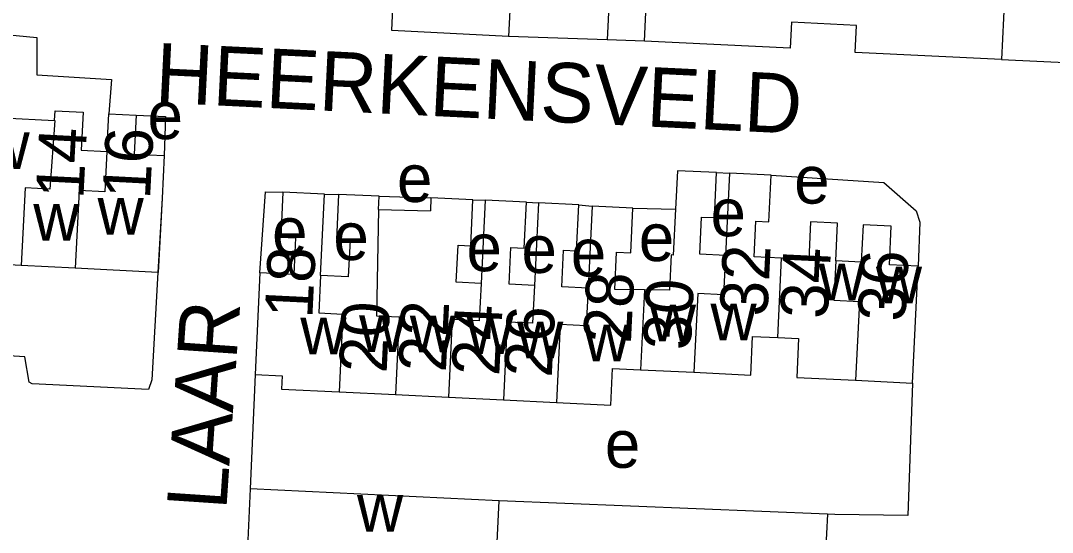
# Model space of a CAD drawing. Extents: x 163026 to 166241, y 382475 to 384501.
# Drawn here: x 164375.5 to 164462, y 383742 to 383784.9 of the extents above; entities that cross this region are included whole.
import ezdxf

# ---------------------------------------------------------------- set-up
doc = ezdxf.new("R2010")
doc.units = 0
for name, color, linetype in [('BLT_Basislijn', 7, 'Continuous'), ('BLT_Bebouwing', 7, 'Continuous'), ('BLT_Centroide', 7, 'Continuous'), ('BLT_Huisnummer', 7, 'Continuous'), ('BLT_Huisnummer_ tussenligend', 7, 'Continuous'), ('BLT_Onderverdeling_panden', 7, 'Continuous'), ('BLT_Straatnaam', 7, 'Continuous')]:
    doc.layers.add(name, color=color, linetype=linetype)

msp = doc.modelspace()

# ---------------------------------------------------------------- linework, layer by layer
at = {"layer": 'BLT_Basislijn'}
for p, q in [((164424.614, 383783.299), (164416.356, 383783.582)), ((164427.758, 383783.191), (164424.614, 383783.299)), ((164457.682, 383781.642), (164463.611, 383781.358)), ((164433.798, 383772.157), (164434.873, 383772.105)), ((164387.308, 383770.014), (164386.961, 383763.762)), ((164400.935, 383770.341), (164402.116, 383770.33)), ((164405.506, 383770.166), (164409.857, 383770.041)), ((164413.373, 383769.87), (164414.4, 383769.834)), ((164417.861, 383769.666), (164418.862, 383769.606)), ((164422.246, 383769.442), (164423.364, 383769.334)), ((164426.791, 383769.168), (164430.358, 383769.099)), ((164395.12, 383755.208), (164394.704, 383745.621)), ((164443.101, 383743.488), (164415.579, 383744.613)), ((164443.101, 383743.488), (164442.919, 383740.26))]:
    msp.add_line(p, q, dxfattribs=at)
for points in [[(164422.167, 383835.909), (164431.749, 383835.494), (164430.679, 383813.13), (164426.089, 383812.971), (164424.614, 383783.299)], [(164362.913, 383784.833), (164376.817, 383783.477), (164376.818, 383780.367), (164383.073, 383779.953), (164382.845, 383777.091)], [(164385.145, 383776.97), (164387.594, 383776.85), (164387.495, 383773.579)], [(164438.364, 383771.936), (164447.831, 383771.316), (164450.521, 383768.939), (164450.84, 383767.983), (164450.688, 383764.303)], [(164395.508, 383763.752), (164395.992, 383770.554), (164397.445, 383770.509)], [(164386.961, 383763.762), (164386.462, 383754.756), (164386.188, 383753.96), (164376.435, 383754.438), (164376.18, 383754.565), (164375.817, 383756.701), (164366.332, 383757.281), (164366.085, 383757.295)], [(164450.213, 383754.502), (164449.833, 383743.398), (164443.726, 383743.462), (164443.101, 383743.488)]]:
    msp.add_lwpolyline(points, dxfattribs=at)
at = {"layer": 'BLT_Bebouwing'}
for p, q in [((164427.758, 383783.191), (164428.052, 383789.269)), ((164416.605, 383788.423), (164416.356, 383783.582)), ((164457.968, 383787.548), (164457.682, 383781.642)), ((164382.845, 383777.091), (164385.145, 383776.97)), ((164387.495, 383773.579), (164387.308, 383770.014)), ((164438.364, 383771.936), (164434.873, 383772.105)), ((164400.935, 383770.341), (164397.445, 383770.509)), ((164387.308, 383770.014), (164386.98, 383763.761)), ((164405.506, 383770.166), (164402.116, 383770.33)), ((164405.453, 383769.068), (164405.506, 383770.166)), ((164409.857, 383770.041), (164409.804, 383768.943)), ((164413.373, 383769.87), (164409.857, 383770.041)), ((164417.861, 383769.666), (164414.4, 383769.834)), ((164422.246, 383769.442), (164418.862, 383769.606)), ((164405.453, 383769.068), (164407.635, 383769.005)), ((164407.635, 383769.005), (164409.804, 383768.943)), ((164426.791, 383769.168), (164423.364, 383769.334)), ((164375.486, 383764.362), (164371.004, 383764.598)), ((164380.014, 383764.126), (164375.486, 383764.362)), ((164450.213, 383754.502), (164450.688, 383764.303)), ((164386.961, 383763.762), (164380.014, 383764.126)), ((164386.98, 383763.761), (164386.961, 383763.762)), ((164395.508, 383763.752), (164395.12, 383755.208)), ((164427.424, 383755.616), (164431.894, 383755.4)), ((164445.46, 383754.731), (164450.213, 383754.502)), ((164402.148, 383753.757), (164406.887, 383753.529)), ((164406.887, 383753.529), (164411.313, 383753.314)), ((164411.313, 383753.314), (164415.929, 383753.09)), ((164415.929, 383753.09), (164420.371, 383752.875)), ((164415.579, 383744.613), (164394.704, 383745.621)), ((164415.282, 383738.463), (164415.579, 383744.613))]:
    msp.add_line(p, q, dxfattribs=at)
for points in [[(164416.356, 383783.582), (164406.572, 383784.084), (164406.7, 383786.582), (164403.505, 383786.746)], [(164457.682, 383781.642), (164445.43, 383782.234), (164445.54, 383784.503), (164440.079, 383784.767), (164439.974, 383782.601), (164427.758, 383783.191)], [(164369.365, 383774.53), (164371.532, 383774.415), (164371.698, 383777.591), (164373.995, 383777.471), (164373.958, 383776.753), (164378.299, 383776.527)], [(164378.299, 383776.527), (164378.342, 383777.336), (164380.695, 383777.213), (164380.529, 383774.043), (164382.68, 383773.93)], [(164382.68, 383773.93), (164382.845, 383777.091)], [(164385.145, 383776.97), (164384.975, 383773.711), (164387.495, 383773.579)], [(164433.798, 383772.157), (164430.514, 383772.316), (164430.358, 383769.099)], [(164434.539, 383765.198), (164432.387, 383765.302), (164432.538, 383768.427), (164433.615, 383768.375), (164433.798, 383772.157)], [(164434.873, 383772.105), (164434.539, 383765.198)], [(164439.248, 383764.962), (164436.959, 383765.074), (164437.104, 383768.07), (164438.174, 383768.018), (164438.364, 383771.936)], [(164397.445, 383770.509), (164397.262, 383766.731), (164398.495, 383766.671), (164398.347, 383763.615), (164395.508, 383763.752)], [(164400.605, 383763.53), (164400.935, 383770.341)], [(164402.116, 383770.33), (164401.932, 383766.544), (164403.069, 383766.489), (164402.921, 383763.418), (164400.605, 383763.53)], [(164414.06, 383762.855), (164411.981, 383762.955), (164412.131, 383766.056), (164413.185, 383766.005), (164413.373, 383769.87)], [(164414.4, 383769.834), (164414.06, 383762.855)], [(164418.525, 383762.695), (164416.406, 383762.798), (164416.554, 383765.861), (164417.675, 383765.807), (164417.861, 383769.666)], [(164418.862, 383769.606), (164418.525, 383762.695)], [(164423.03, 383762.465), (164420.829, 383762.574), (164420.977, 383765.642), (164422.06, 383765.59), (164422.246, 383769.442)], [(164423.364, 383769.334), (164423.03, 383762.465)], [(164427.745, 383762.311), (164425.267, 383762.339), (164425.419, 383765.489), (164426.61, 383765.432), (164426.791, 383769.168)], [(164430.358, 383769.099), (164430.171, 383765.236), (164430.001, 383765.244), (164429.858, 383762.287), (164427.745, 383762.311)], [(164443.79, 383764.745), (164443.944, 383767.916), (164441.687, 383768.026), (164441.533, 383764.852), (164439.248, 383764.962)], [(164450.688, 383764.303), (164448.287, 383764.419), (164448.443, 383767.657), (164446.085, 383767.771), (164445.934, 383764.642), (164443.79, 383764.745)], [(164431.894, 383755.4), (164436.664, 383755.169), (164436.821, 383758.411), (164438.927, 383758.309)], [(164438.927, 383758.309), (164440.679, 383758.224), (164440.522, 383754.971), (164445.46, 383754.731)], [(164420.371, 383752.875), (164424.923, 383752.656), (164425.072, 383755.73), (164427.424, 383755.616)], [(164395.12, 383755.208), (164397.386, 383755.1), (164397.332, 383753.992), (164402.148, 383753.757)], [(164394.704, 383745.621), (164394.407, 383739.471), (164415.282, 383738.463)]]:
    msp.add_lwpolyline(points, dxfattribs=at)
at = {"layer": 'BLT_Onderverdeling_panden'}
for p, q in [((164438.927, 383758.309), (164439.248, 383764.962)), ((164427.745, 383762.311), (164427.424, 383755.616))]:
    msp.add_line(p, q, dxfattribs=at)
for points in [[(164378.299, 383776.527), (164378.326, 383776.526), (164377.898, 383770.774), (164375.828, 383770.883), (164375.486, 383764.362)], [(164382.68, 383773.93), (164382.503, 383770.532), (164380.353, 383770.645), (164380.014, 383764.126)], [(164405.453, 383769.068), (164405.297, 383760.142), (164407.195, 383760.052), (164406.887, 383753.529)], [(164434.539, 383765.198), (164434.38, 383761.897), (164432.222, 383762.004), (164431.894, 383755.4)], [(164443.79, 383764.745), (164443.629, 383761.453), (164445.777, 383761.35), (164445.46, 383754.731)], [(164400.605, 383763.53), (164400.452, 383760.378), (164402.467, 383760.28), (164402.148, 383753.757)], [(164414.06, 383762.855), (164413.908, 383759.727), (164411.629, 383759.838), (164411.313, 383753.314)], [(164418.525, 383762.695), (164418.371, 383759.511), (164416.249, 383759.614), (164415.929, 383753.09)], [(164423.03, 383762.465), (164422.875, 383759.293), (164420.68, 383759.4), (164420.371, 383752.875)]]:
    msp.add_lwpolyline(points, dxfattribs=at)

# ---------------------------------------------------------------- texts
at = {"layer": 'BLT_Centroide'}
for s, p in [('e', (164386.094, 383774.963)), ('w', (164372.346, 383772.467)), ('e', (164407.004, 383769.686)), ('e', (164440.305, 383769.556)), ('w', (164376.521, 383766.437)), ('w', (164381.906, 383766.943)), ('e', (164433.29, 383766.818)), ('e', (164396.532, 383765.25)), ('e', (164401.677, 383764.818)), ('e', (164427.278, 383764.733)), ('e', (164412.834, 383763.882)), ('e', (164417.44, 383763.738)), ('e', (164421.579, 383763.45)), ('w', (164442.359, 383761.438)), ('w', (164447.156, 383761.188)), ('w', (164428.204, 383757.999)), ('w', (164433.29, 383758.087)), ('w', (164403.828, 383757.116)), ('w', (164408.083, 383757.08)), ('w', (164412.87, 383756.936)), ('w', (164398.906, 383756.9)), ('w', (164417.081, 383756.576)), ('w', (164422.659, 383756.324)), ('e', (164424.433, 383747.389)), ('w', (164403.659, 383742.031))]:
    msp.add_text(s, height=4, dxfattribs=at).set_placement(p)
at = {"layer": 'BLT_Huisnummer'}
for s, height, rotation, p in [('16', 4, 87.01183, (164386.297, 383769.871)), ('18', 3.9999, 87.23147, (164399.905, 383759.875)), ('36', 3.9999, 87.23147, (164449.617, 383759.609)), ('30', 3.9999, 87.23147, (164431.617, 383757.206)), ('22', 3.9999, 87.23147, (164411.102, 383755.366)), ('26', 3.9999, 87.23147, (164419.977, 383754.926))]:
    msp.add_text(s, height=height, rotation=rotation, dxfattribs=at).set_placement(p)
at = {"layer": 'BLT_Huisnummer_ tussenligend'}
for s, height, rotation, p in [('14', 4, 87.01183, (164380.708, 383769.896)), ('32', 3.9999, 87.23147, (164438.051, 383760.04)), ('34', 3.9999, 87.23147, (164443.106, 383759.836)), ('28', 3.9999, 87.23147, (164426.614, 383757.772)), ('20', 3.9999, 87.23147, (164406.133, 383755.289)), ('24', 3.9999, 87.23147, (164415.576, 383755.051))]:
    msp.add_text(s, height=height, rotation=rotation, dxfattribs=at).set_placement(p)
at = {"layer": 'BLT_Straatnaam'}
for s, rotation, p in [('HEERKENSVELD', 357.19478, (164386.662, 383778.047)), ('LAAR', 86.1433, (164392.697, 383743.8))]:
    msp.add_text(s, height=5, rotation=rotation, dxfattribs=at).set_placement(p)

doc.saveas('drawing.dxf')
